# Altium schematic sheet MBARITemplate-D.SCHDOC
size D; Organization: Monterey Bay Aquarium Research Institute; Address1: 7700 Sandholdt Rd; Address2: Moss Landing, CA 95039-9644; CompanyName: MBARI
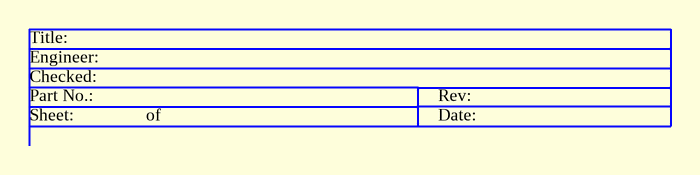
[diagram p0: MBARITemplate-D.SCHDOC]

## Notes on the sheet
- Title:
- Sheet:
- Engineer:
- Part No.:
- Checked:
- of
- Rev:
- Date:
